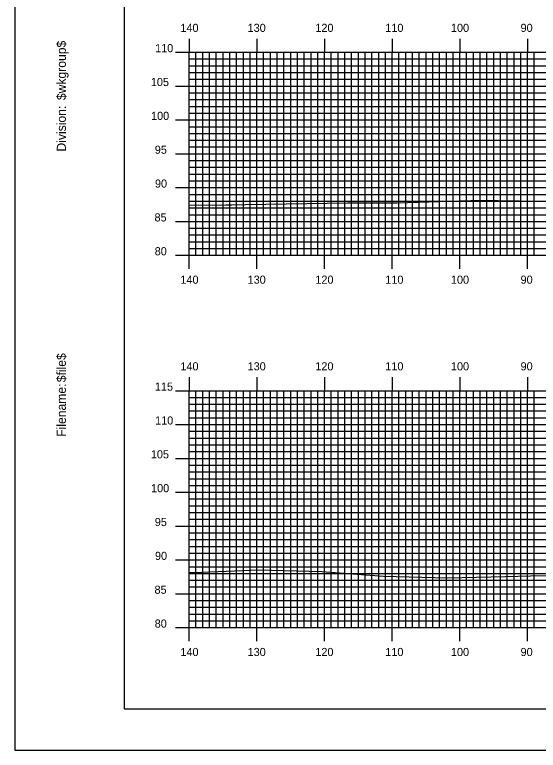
# Model space of a CAD drawing. Extents: x 1763365 to 1763708, y 442591 to 442811.
# Drawn here: x 1763365 to 1763442.4, y 442590.5 to 442699.2 of the extents above; entities that cross this region are included whole.
import ezdxf

# ---------------------------------------------------------------- set-up
doc = ezdxf.new("R2010")
doc.units = 0
for name, color, linetype in [('BORDER', 7, 'Continuous'), ('H_V ANNOTATION', 7, 'Continuous'), ('MAJOR', 7, 'Continuous'), ('MINOR', 7, 'Continuous'), ('PLOT BOUNDARY', 7, 'Continuous'), ('S_Roadway_Centerline', 7, 'Continuous')]:
    doc.layers.add(name, color=color, linetype=linetype)

msp = doc.modelspace()

# ---------------------------------------------------------------- linework, layer by layer
at = {"layer": 'BORDER'}
msp.add_lwpolyline([(1763381.21, 442596.67), (1763701.21, 442596.67), (1763701.21, 442806.67), (1763381.21, 442806.67)], close=True, dxfattribs=at)
at = {"layer": 'MAJOR'}
for p, q in [((1763390.81, 442695.67), (1763390.81, 442693.67)), ((1763400.81, 442695.67), (1763400.81, 442693.67)), ((1763410.81, 442695.67), (1763410.81, 442693.67)), ((1763420.81, 442695.67), (1763420.81, 442693.67)), ((1763430.81, 442695.67), (1763430.81, 442693.67)), ((1763440.81, 442695.67), (1763440.81, 442693.67)), ((1763388.8, 442693.67), (1763390.81, 442693.67)), ((1763390.81, 442693.67), (1763670.81, 442693.67)), ((1763390.81, 442663.67), (1763390.81, 442693.67)), ((1763390.81, 442663.67), (1763390.81, 442693.67)), ((1763390.81, 442693.67), (1763670.81, 442693.67)), ((1763400.81, 442663.67), (1763400.81, 442693.67)), ((1763410.81, 442663.67), (1763410.81, 442693.67)), ((1763420.81, 442663.67), (1763420.81, 442693.67)), ((1763430.81, 442663.67), (1763430.81, 442693.67)), ((1763440.81, 442663.67), (1763440.81, 442693.67)), ((1763388.8, 442688.67), (1763390.81, 442688.67)), ((1763390.81, 442688.67), (1763670.81, 442688.67)), ((1763388.8, 442683.67), (1763390.81, 442683.67)), ((1763390.81, 442683.67), (1763670.81, 442683.67)), ((1763388.8, 442678.67), (1763390.81, 442678.67)), ((1763390.81, 442678.67), (1763670.81, 442678.67)), ((1763388.8, 442673.67), (1763390.81, 442673.67)), ((1763390.81, 442673.67), (1763670.81, 442673.67)), ((1763388.8, 442668.67), (1763390.81, 442668.67)), ((1763390.81, 442668.67), (1763670.81, 442668.67)), ((1763388.8, 442663.67), (1763390.81, 442663.67)), ((1763390.81, 442663.67), (1763670.81, 442663.67)), ((1763390.81, 442663.67), (1763670.81, 442663.67)), ((1763390.81, 442661.66), (1763390.81, 442663.67)), ((1763400.81, 442661.66), (1763400.81, 442663.67)), ((1763410.81, 442661.66), (1763410.81, 442663.67)), ((1763420.81, 442661.66), (1763420.81, 442663.67)), ((1763430.81, 442661.66), (1763430.81, 442663.67)), ((1763440.81, 442661.66), (1763440.81, 442663.67)), ((1763390.81, 442645.67), (1763390.81, 442643.67)), ((1763400.81, 442645.67), (1763400.81, 442643.67)), ((1763410.81, 442645.67), (1763410.81, 442643.67)), ((1763420.81, 442645.67), (1763420.81, 442643.67)), ((1763430.81, 442645.67), (1763430.81, 442643.67)), ((1763440.81, 442645.67), (1763440.81, 442643.67)), ((1763388.8, 442643.67), (1763390.81, 442643.67)), ((1763390.81, 442643.67), (1763670.81, 442643.67)), ((1763390.81, 442608.67), (1763390.81, 442643.67)), ((1763390.81, 442608.67), (1763390.81, 442643.67)), ((1763390.81, 442643.67), (1763670.81, 442643.67)), ((1763400.81, 442608.67), (1763400.81, 442643.67)), ((1763410.81, 442608.67), (1763410.81, 442643.67)), ((1763420.81, 442608.67), (1763420.81, 442643.67)), ((1763430.81, 442608.67), (1763430.81, 442643.67)), ((1763440.81, 442608.67), (1763440.81, 442643.67)), ((1763388.8, 442638.67), (1763390.81, 442638.67)), ((1763390.81, 442638.67), (1763670.81, 442638.67)), ((1763388.8, 442633.67), (1763390.81, 442633.67)), ((1763390.81, 442633.67), (1763670.81, 442633.67)), ((1763388.8, 442628.67), (1763390.81, 442628.67)), ((1763390.81, 442628.67), (1763670.81, 442628.67)), ((1763388.8, 442623.67), (1763390.81, 442623.67)), ((1763390.81, 442623.67), (1763670.81, 442623.67)), ((1763388.8, 442618.67), (1763390.81, 442618.67)), ((1763390.81, 442618.67), (1763670.81, 442618.67)), ((1763388.8, 442613.67), (1763390.81, 442613.67)), ((1763390.81, 442613.67), (1763670.81, 442613.67)), ((1763388.8, 442608.67), (1763390.81, 442608.67)), ((1763390.81, 442608.67), (1763670.81, 442608.67)), ((1763390.81, 442608.67), (1763670.81, 442608.67)), ((1763390.81, 442606.66), (1763390.81, 442608.67)), ((1763400.81, 442606.66), (1763400.81, 442608.67)), ((1763410.81, 442606.66), (1763410.81, 442608.67)), ((1763420.81, 442606.66), (1763420.81, 442608.67)), ((1763430.81, 442606.66), (1763430.81, 442608.67)), ((1763440.81, 442606.66), (1763440.81, 442608.67))]:
    msp.add_line(p, q, dxfattribs=at)
at = {"layer": 'MINOR'}
for p, q in [((1763391.81, 442663.67), (1763391.81, 442693.67)), ((1763392.81, 442663.67), (1763392.81, 442693.67)), ((1763393.81, 442663.67), (1763393.81, 442693.67)), ((1763394.81, 442663.67), (1763394.81, 442693.67)), ((1763395.81, 442663.67), (1763395.81, 442693.67)), ((1763396.81, 442663.67), (1763396.81, 442693.67)), ((1763397.81, 442663.67), (1763397.81, 442693.67)), ((1763398.81, 442663.67), (1763398.81, 442693.67)), ((1763399.81, 442663.67), (1763399.81, 442693.67)), ((1763401.81, 442663.67), (1763401.81, 442693.67)), ((1763402.81, 442663.67), (1763402.81, 442693.67)), ((1763403.81, 442663.67), (1763403.81, 442693.67)), ((1763404.81, 442663.67), (1763404.81, 442693.67)), ((1763405.81, 442663.67), (1763405.81, 442693.67)), ((1763406.81, 442663.67), (1763406.81, 442693.67)), ((1763407.81, 442663.67), (1763407.81, 442693.67)), ((1763408.81, 442663.67), (1763408.81, 442693.67)), ((1763409.81, 442663.67), (1763409.81, 442693.67)), ((1763411.81, 442663.67), (1763411.81, 442693.67)), ((1763412.81, 442663.67), (1763412.81, 442693.67)), ((1763413.81, 442663.67), (1763413.81, 442693.67)), ((1763414.81, 442663.67), (1763414.81, 442693.67)), ((1763415.81, 442663.67), (1763415.81, 442693.67)), ((1763416.81, 442663.67), (1763416.81, 442693.67)), ((1763417.81, 442663.67), (1763417.81, 442693.67)), ((1763418.81, 442663.67), (1763418.81, 442693.67)), ((1763419.81, 442663.67), (1763419.81, 442693.67)), ((1763421.81, 442663.67), (1763421.81, 442693.67)), ((1763422.81, 442663.67), (1763422.81, 442693.67)), ((1763423.81, 442663.67), (1763423.81, 442693.67)), ((1763424.81, 442663.67), (1763424.81, 442693.67)), ((1763425.81, 442663.67), (1763425.81, 442693.67)), ((1763426.81, 442663.67), (1763426.81, 442693.67)), ((1763427.81, 442663.67), (1763427.81, 442693.67)), ((1763428.81, 442663.67), (1763428.81, 442693.67)), ((1763429.81, 442663.67), (1763429.81, 442693.67)), ((1763431.81, 442663.67), (1763431.81, 442693.67)), ((1763432.81, 442663.67), (1763432.81, 442693.67)), ((1763433.81, 442663.67), (1763433.81, 442693.67)), ((1763434.81, 442663.67), (1763434.81, 442693.67)), ((1763435.81, 442663.67), (1763435.81, 442693.67)), ((1763436.81, 442663.67), (1763436.81, 442693.67)), ((1763437.81, 442663.67), (1763437.81, 442693.67)), ((1763438.81, 442663.67), (1763438.81, 442693.67)), ((1763439.81, 442663.67), (1763439.81, 442693.67)), ((1763441.81, 442663.67), (1763441.81, 442693.67)), ((1763390.81, 442692.67), (1763670.81, 442692.67)), ((1763390.81, 442692.67), (1763392.81, 442692.67)), ((1763390.81, 442691.67), (1763670.81, 442691.67)), ((1763390.81, 442691.67), (1763392.81, 442691.67)), ((1763390.81, 442690.67), (1763670.81, 442690.67)), ((1763390.81, 442690.67), (1763392.81, 442690.67)), ((1763390.81, 442689.67), (1763670.81, 442689.67)), ((1763390.81, 442689.67), (1763392.81, 442689.67)), ((1763390.81, 442687.67), (1763670.81, 442687.67)), ((1763390.81, 442687.67), (1763392.81, 442687.67)), ((1763390.81, 442686.67), (1763670.81, 442686.67)), ((1763390.81, 442686.67), (1763392.81, 442686.67)), ((1763390.81, 442685.67), (1763670.81, 442685.67)), ((1763390.81, 442685.67), (1763392.81, 442685.67)), ((1763390.81, 442684.67), (1763670.81, 442684.67)), ((1763390.81, 442684.67), (1763392.81, 442684.67)), ((1763390.81, 442682.67), (1763670.81, 442682.67)), ((1763390.81, 442682.67), (1763392.81, 442682.67)), ((1763390.81, 442681.67), (1763670.81, 442681.67)), ((1763390.81, 442681.67), (1763392.81, 442681.67)), ((1763390.81, 442680.67), (1763670.81, 442680.67)), ((1763390.81, 442680.67), (1763392.81, 442680.67)), ((1763390.81, 442679.67), (1763670.81, 442679.67)), ((1763390.81, 442679.67), (1763392.81, 442679.67)), ((1763390.81, 442677.67), (1763670.81, 442677.67)), ((1763390.81, 442677.67), (1763392.81, 442677.67)), ((1763390.81, 442676.67), (1763670.81, 442676.67)), ((1763390.81, 442676.67), (1763392.81, 442676.67)), ((1763390.81, 442675.67), (1763670.81, 442675.67)), ((1763390.81, 442675.67), (1763392.81, 442675.67)), ((1763390.81, 442674.67), (1763670.81, 442674.67)), ((1763390.81, 442674.67), (1763392.81, 442674.67)), ((1763390.81, 442672.67), (1763670.81, 442672.67)), ((1763390.81, 442672.67), (1763392.81, 442672.67)), ((1763390.81, 442671.67), (1763670.81, 442671.67)), ((1763390.81, 442671.67), (1763392.81, 442671.67)), ((1763390.81, 442670.67), (1763670.81, 442670.67)), ((1763390.81, 442670.67), (1763392.81, 442670.67)), ((1763390.81, 442669.67), (1763670.81, 442669.67)), ((1763390.81, 442669.67), (1763392.81, 442669.67)), ((1763390.81, 442667.67), (1763670.81, 442667.67)), ((1763390.81, 442667.67), (1763392.81, 442667.67)), ((1763390.81, 442666.67), (1763670.81, 442666.67)), ((1763390.81, 442666.67), (1763392.81, 442666.67)), ((1763390.81, 442665.67), (1763670.81, 442665.67)), ((1763390.81, 442665.67), (1763392.81, 442665.67)), ((1763390.81, 442664.67), (1763670.81, 442664.67)), ((1763390.81, 442664.67), (1763392.81, 442664.67)), ((1763391.81, 442608.67), (1763391.81, 442643.67)), ((1763392.81, 442608.67), (1763392.81, 442643.67)), ((1763393.81, 442608.67), (1763393.81, 442643.67)), ((1763394.81, 442608.67), (1763394.81, 442643.67)), ((1763395.81, 442608.67), (1763395.81, 442643.67)), ((1763396.81, 442608.67), (1763396.81, 442643.67)), ((1763397.81, 442608.67), (1763397.81, 442643.67)), ((1763398.81, 442608.67), (1763398.81, 442643.67)), ((1763399.81, 442608.67), (1763399.81, 442643.67)), ((1763401.81, 442608.67), (1763401.81, 442643.67)), ((1763402.81, 442608.67), (1763402.81, 442643.67)), ((1763403.81, 442608.67), (1763403.81, 442643.67)), ((1763404.81, 442608.67), (1763404.81, 442643.67)), ((1763405.81, 442608.67), (1763405.81, 442643.67)), ((1763406.81, 442608.67), (1763406.81, 442643.67)), ((1763407.81, 442608.67), (1763407.81, 442643.67)), ((1763408.81, 442608.67), (1763408.81, 442643.67)), ((1763409.81, 442608.67), (1763409.81, 442643.67)), ((1763411.81, 442608.67), (1763411.81, 442643.67)), ((1763412.81, 442608.67), (1763412.81, 442643.67)), ((1763413.81, 442608.67), (1763413.81, 442643.67)), ((1763414.81, 442608.67), (1763414.81, 442643.67)), ((1763415.81, 442608.67), (1763415.81, 442643.67)), ((1763416.81, 442608.67), (1763416.81, 442643.67)), ((1763417.81, 442608.67), (1763417.81, 442643.67)), ((1763418.81, 442608.67), (1763418.81, 442643.67)), ((1763419.81, 442608.67), (1763419.81, 442643.67)), ((1763421.81, 442608.67), (1763421.81, 442643.67)), ((1763422.81, 442608.67), (1763422.81, 442643.67)), ((1763423.81, 442608.67), (1763423.81, 442643.67)), ((1763424.81, 442608.67), (1763424.81, 442643.67)), ((1763425.81, 442608.67), (1763425.81, 442643.67)), ((1763426.81, 442608.67), (1763426.81, 442643.67)), ((1763427.81, 442608.67), (1763427.81, 442643.67)), ((1763428.81, 442608.67), (1763428.81, 442643.67)), ((1763429.81, 442608.67), (1763429.81, 442643.67)), ((1763431.81, 442608.67), (1763431.81, 442643.67)), ((1763432.81, 442608.67), (1763432.81, 442643.67)), ((1763433.81, 442608.67), (1763433.81, 442643.67)), ((1763434.81, 442608.67), (1763434.81, 442643.67)), ((1763435.81, 442608.67), (1763435.81, 442643.67)), ((1763436.81, 442608.67), (1763436.81, 442643.67)), ((1763437.81, 442608.67), (1763437.81, 442643.67)), ((1763438.81, 442608.67), (1763438.81, 442643.67)), ((1763439.81, 442608.67), (1763439.81, 442643.67)), ((1763441.81, 442608.67), (1763441.81, 442643.67)), ((1763390.81, 442642.67), (1763670.81, 442642.67)), ((1763390.81, 442642.67), (1763392.81, 442642.67)), ((1763390.81, 442641.67), (1763670.81, 442641.67)), ((1763390.81, 442641.67), (1763392.81, 442641.67)), ((1763390.81, 442640.67), (1763670.81, 442640.67)), ((1763390.81, 442640.67), (1763392.81, 442640.67)), ((1763390.81, 442639.67), (1763670.81, 442639.67)), ((1763390.81, 442639.67), (1763392.81, 442639.67)), ((1763390.81, 442637.67), (1763670.81, 442637.67)), ((1763390.81, 442637.67), (1763392.81, 442637.67)), ((1763390.81, 442636.67), (1763670.81, 442636.67)), ((1763390.81, 442636.67), (1763392.81, 442636.67)), ((1763390.81, 442635.67), (1763670.81, 442635.67)), ((1763390.81, 442635.67), (1763392.81, 442635.67)), ((1763390.81, 442634.67), (1763670.81, 442634.67)), ((1763390.81, 442634.67), (1763392.81, 442634.67)), ((1763390.81, 442632.67), (1763670.81, 442632.67)), ((1763390.81, 442632.67), (1763392.81, 442632.67)), ((1763390.81, 442631.67), (1763670.81, 442631.67)), ((1763390.81, 442631.67), (1763392.81, 442631.67)), ((1763390.81, 442630.67), (1763670.81, 442630.67)), ((1763390.81, 442630.67), (1763392.81, 442630.67)), ((1763390.81, 442629.67), (1763670.81, 442629.67)), ((1763390.81, 442629.67), (1763392.81, 442629.67)), ((1763390.81, 442627.67), (1763670.81, 442627.67)), ((1763390.81, 442627.67), (1763392.81, 442627.67)), ((1763390.81, 442626.67), (1763670.81, 442626.67)), ((1763390.81, 442626.67), (1763392.81, 442626.67)), ((1763390.81, 442625.67), (1763670.81, 442625.67)), ((1763390.81, 442625.67), (1763392.81, 442625.67)), ((1763390.81, 442624.67), (1763670.81, 442624.67)), ((1763390.81, 442624.67), (1763392.81, 442624.67)), ((1763390.81, 442622.67), (1763670.81, 442622.67)), ((1763390.81, 442622.67), (1763392.81, 442622.67)), ((1763390.81, 442621.67), (1763670.81, 442621.67)), ((1763390.81, 442621.67), (1763392.81, 442621.67)), ((1763390.81, 442620.67), (1763670.81, 442620.67)), ((1763390.81, 442620.67), (1763392.81, 442620.67)), ((1763390.81, 442619.67), (1763670.81, 442619.67)), ((1763390.81, 442619.67), (1763392.81, 442619.67)), ((1763390.81, 442617.67), (1763670.81, 442617.67)), ((1763390.81, 442617.67), (1763392.81, 442617.67)), ((1763390.81, 442616.67), (1763670.81, 442616.67)), ((1763390.81, 442616.67), (1763392.81, 442616.67)), ((1763390.81, 442615.67), (1763670.81, 442615.67)), ((1763390.81, 442615.67), (1763392.81, 442615.67)), ((1763390.81, 442614.67), (1763670.81, 442614.67)), ((1763390.81, 442614.67), (1763392.81, 442614.67)), ((1763390.81, 442612.67), (1763670.81, 442612.67)), ((1763390.81, 442612.67), (1763392.81, 442612.67)), ((1763390.81, 442611.67), (1763670.81, 442611.67)), ((1763390.81, 442611.67), (1763392.81, 442611.67)), ((1763390.81, 442610.67), (1763670.81, 442610.67)), ((1763390.81, 442610.67), (1763392.81, 442610.67)), ((1763390.81, 442609.67), (1763670.81, 442609.67)), ((1763390.81, 442609.67), (1763392.81, 442609.67))]:
    msp.add_line(p, q, dxfattribs=at)
at = {"layer": 'PLOT BOUNDARY'}
msp.add_lwpolyline([(1763365.02, 442590.55), (1763705.02, 442590.55), (1763705.02, 442810.55), (1763365.02, 442810.55)], close=True, dxfattribs=at)
at = {"layer": 'S_Roadway_Centerline'}
for points in [[(1763390.81, 442671.09), (1763396.2, 442671.13), (1763397.1, 442671.12), (1763399.15, 442671.17), (1763414.19, 442671.44), (1763421.53, 442671.4), (1763432.42, 442671.76), (1763432.89, 442671.78), (1763436.46, 442671.75), (1763445.87, 442671.61)], [(1763390.81, 442616.81), (1763392.68, 442616.84), (1763401.08, 442617.2), (1763410.4, 442616.94), (1763419.52, 442616.26), (1763428.97, 442616.03), (1763437.53, 442616.22), (1763441.27, 442616.31), (1763448.53, 442616.4)]]:
    msp.add_lwpolyline(points, dxfattribs=at)

# ---------------------------------------------------------------- texts
at = {"layer": 'BORDER'}
for s, p in [('$wkgroup$', (1763372.58, 442686.6)), ('Division:', (1763372.58, 442679)), ('$file$', (1763372.58, 442644.92)), ('Filename:', (1763372.58, 442636.86))]:
    msp.add_text(s, height=1.339, rotation=90, dxfattribs=at).set_placement(p)
at = {"layer": 'H_V ANNOTATION'}
for s, p in [('140', (1763389.51, 442696.67)), ('130', (1763399.44, 442696.67)), ('120', (1763409.45, 442696.67)), ('110', (1763419.79, 442696.67)), ('100', (1763429.49, 442696.67)), ('90', (1763439.78, 442696.67)), ('110', (1763385.77, 442693.67)), ('105', (1763385.14, 442688.67)), ('100', (1763385.17, 442683.67)), ('95', (1763385.72, 442678.67)), ('90', (1763385.75, 442673.67)), ('85', (1763385.68, 442668.67)), ('80', (1763385.71, 442663.67)), ('140', (1763389.51, 442659.47)), ('130', (1763399.44, 442659.47)), ('120', (1763409.45, 442659.47)), ('110', (1763419.79, 442659.47)), ('100', (1763429.49, 442659.47)), ('90', (1763439.78, 442659.47)), ('140', (1763389.51, 442646.67)), ('130', (1763399.44, 442646.67)), ('120', (1763409.45, 442646.67)), ('110', (1763419.79, 442646.67)), ('100', (1763429.49, 442646.67)), ('90', (1763439.78, 442646.67)), ('115', (1763385.74, 442643.67)), ('110', (1763385.77, 442638.67)), ('105', (1763385.14, 442633.67)), ('100', (1763385.17, 442628.67)), ('95', (1763385.72, 442623.67)), ('90', (1763385.75, 442618.67)), ('85', (1763385.68, 442613.67)), ('80', (1763385.71, 442608.67)), ('140', (1763389.51, 442604.47)), ('130', (1763399.44, 442604.47)), ('120', (1763409.45, 442604.47)), ('110', (1763419.79, 442604.47)), ('100', (1763429.49, 442604.47)), ('90', (1763439.78, 442604.47))]:
    msp.add_text(s, height=1.2, dxfattribs=at).set_placement(p)
at = {"layer": 'MAJOR'}
for p in [(1763390.8, 442663.67), (1763390.8, 442608.67)]:
    msp.add_text('-', height=0.012, dxfattribs=at).set_placement(p)

doc.saveas('drawing.dxf')
